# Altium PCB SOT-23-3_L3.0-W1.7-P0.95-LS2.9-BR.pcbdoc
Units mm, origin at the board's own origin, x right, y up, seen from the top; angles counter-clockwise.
Board outline 16.07 x 15.79 mm, 2 copper layers (Top Layer, Bottom Layer), stack 0 mm thick; 1 components, 0 nets, 3 pads, 0 vias.
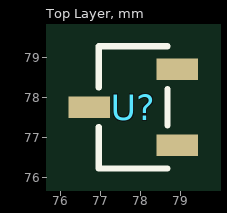
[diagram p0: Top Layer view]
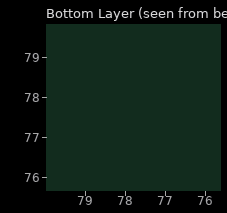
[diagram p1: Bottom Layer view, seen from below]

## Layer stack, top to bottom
Top Layer: signal copper (thickness not stored)
Bottom Layer: signal copper (thickness not stored)

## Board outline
85.92,69.85 69.85,69.85 69.85,85.636 85.92,85.636

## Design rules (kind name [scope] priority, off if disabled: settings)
PasteMaskExpansion "Paste Mask Expansion" [All] p1: expansion=0
SolderMaskExpansion "Solder Mask Expansion" [IsVia] p1: expansion=-25.4 istentingtop=TRUE
SolderMaskExpansion "Solder Mask Expansion" [All] p2: expansion=0.051 istentingtop=FALSE

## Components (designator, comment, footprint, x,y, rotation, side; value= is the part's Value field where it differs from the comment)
U? "" SOT-23-3_L3.0-W1.7-P0.95-LS2.9-BR 77.82,77.76 r0 top

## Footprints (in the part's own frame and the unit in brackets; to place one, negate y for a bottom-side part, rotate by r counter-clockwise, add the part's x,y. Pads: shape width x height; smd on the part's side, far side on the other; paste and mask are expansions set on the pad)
SOT-23-3_L3.0-W1.7-P0.95-LS2.9-BR [mm]
  rect 1.037x0.532 smd: 1(1.101,-0.95) 2(1.101,0.95) 3(-1.101,0)
  silkscreen extent -0.86,-1.53 0.86,1.53

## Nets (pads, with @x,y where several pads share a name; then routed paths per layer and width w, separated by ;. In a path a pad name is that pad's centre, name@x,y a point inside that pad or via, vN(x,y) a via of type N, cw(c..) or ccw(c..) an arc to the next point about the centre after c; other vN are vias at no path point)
pads on no net: U?.1 U?.2 U?.3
